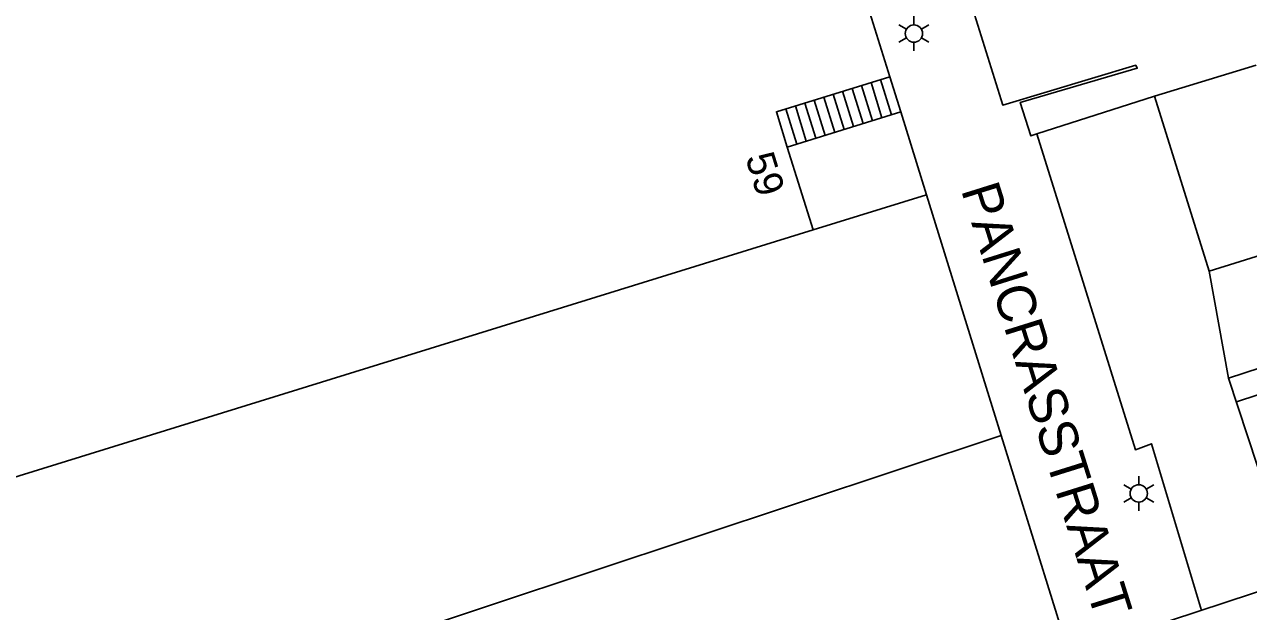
# Model space of a CAD drawing. Extents: x 122462 to 123306, y 485548 to 486417.
# Drawn here: x 122661.2 to 122724.7, y 486167.9 to 486198.4 of the extents above; entities that cross this region are included whole.
import ezdxf

# ---------------------------------------------------------------- set-up
doc = ezdxf.new("R2010")
doc.units = 0
for name, color, linetype in [('B-WE-AL-WERKGRENS-G', 7, 'Continuous'), ('B-WE-IE-MEUBILAIR_WEGMEUBILAIR_VERKEERSBORD-S', 7, 'Continuous'), ('Level 1', 7, 'Continuous'), ('Level 17', 7, 'Continuous'), ('Level 31', 7, 'Continuous'), ('Level 33', 7, 'Continuous'), ('Level 4', 7, 'Continuous'), ('Level 50', 7, 'Continuous'), ('N werkgrens', 7, 'Continuous'), ('N-WE-AL-T25', 7, 'Continuous'), ('N-WE-GR-BOOM_DOORWORTELBARE RUIMTE-G', 7, 'Continuous')]:
    doc.layers.add(name, color=color, linetype=linetype)

msp = doc.modelspace()

# ---------------------------------------------------------------- linework, layer by layer
at = {"layer": 'B-WE-AL-WERKGRENS-G'}
msp.add_lwpolyline([(122857.632, 486078.279), (122830.484, 486160.606), (122900.937, 486183.81), (122887.855, 486222.555), (122665.445, 486149.273), (122678.196, 486110.449), (122807.072, 486152.895), (122835.324, 486068.154)], dxfattribs=at)
at = {"layer": 'Level 1'}
for p, q in [((122702.294, 486207.955), (122706.11, 486195.719)), ((122725.118, 486196.312), (122719.85, 486194.699)), ((122719.85, 486194.699), (122722.685, 486185.626)), ((122700.779, 486192.059), (122702.13, 486187.759)), ((122702.13, 486187.759), (122708.009, 486189.59)), ((122708.009, 486189.59), (122711.887, 486177.083)), ((122722.685, 486185.626), (122727.035, 486186.985)), ((122727.016, 486181.156), (122723.689, 486180.059)), ((122723.689, 486180.059), (122727.121, 486169.595))]:
    msp.add_line(p, q, dxfattribs=at)
for points in [[(122706.11, 486195.719), (122700.214, 486193.893), (122700.779, 486192.059)], [(122711.887, 486177.083), (122715.406, 486165.734)]]:
    msp.add_lwpolyline(points, dxfattribs=at)
at = {"layer": 'Level 17'}
msp.add_line((122719.85, 486194.699), (122713.74, 486192.745), dxfattribs=at)
for points in [[(122713.74, 486192.745), (122713.421, 486192.643), (122712.875, 486194.383), (122718.945, 486196.153), (122718.874, 486196.31), (122711.969, 486194.245), (122710.502, 486198.949), (122710.098, 486200.244), (122712.007, 486200.847), (122712.285, 486199.973)], [(122713.74, 486192.745), (122718.856, 486176.345), (122719.681, 486176.651), (122722.283, 486168)]]:
    msp.add_lwpolyline(points, dxfattribs=at)
at = {"layer": 'Level 31'}
for p, q in [((122706.11, 486195.719), (122706.679, 486193.89)), ((122706.679, 486193.89), (122700.779, 486192.059))]:
    msp.add_line(p, q, dxfattribs=at)
at = {"layer": 'Level 33'}
for p, q in [((122704.146, 486195.112), (122704.714, 486193.281)), ((122704.638, 486195.264), (122705.206, 486193.433)), ((122705.128, 486195.417), (122705.696, 486193.585)), ((122705.62, 486195.569), (122706.188, 486193.738)), ((122702.18, 486194.503), (122702.748, 486192.671)), ((122702.672, 486194.655), (122703.24, 486192.824)), ((122703.163, 486194.807), (122703.731, 486192.976)), ((122703.654, 486194.96), (122704.222, 486193.128)), ((122700.706, 486194.045), (122701.274, 486192.214)), ((122701.198, 486194.198), (122701.766, 486192.367)), ((122701.689, 486194.35), (122702.257, 486192.519))]:
    msp.add_line(p, q, dxfattribs=at)
at = {"layer": 'Level 4'}
msp.add_lwpolyline([(122634.662, 486153.891), (122630.945, 486165.712), (122702.13, 486187.759)], dxfattribs=at)
at = {"layer": 'Level 50'}
for p, q in [((122706.963, 486198.184), (122706.573, 486198.409)), ((122707.353, 486198.409), (122707.353, 486198.859)), ((122708.132, 486198.409), (122707.742, 486198.184)), ((122706.963, 486197.734), (122706.573, 486197.509)), ((122708.132, 486197.509), (122707.742, 486197.734)), ((122707.353, 486197.059), (122707.353, 486197.509)), ((122719.028, 486174.523), (122719.028, 486174.973)), ((122718.638, 486174.298), (122718.248, 486174.523)), ((122719.807, 486174.523), (122719.417, 486174.298)), ((122718.638, 486173.848), (122718.248, 486173.623)), ((122719.028, 486173.173), (122719.028, 486173.623)), ((122719.807, 486173.623), (122719.417, 486173.848))]:
    msp.add_line(p, q, dxfattribs=at)
for centre in [(122707.353, 486197.959), (122719.028, 486174.073)]:
    msp.add_circle(centre, 0.45, dxfattribs=at)
at = {"layer": 'N werkgrens'}
for p, q in [((122706.679, 486193.89), (122708.009, 486189.59)), ((122722.685, 486185.626), (122723.689, 486180.059))]:
    msp.add_line(p, q, dxfattribs=at)
at = {"layer": 'N-WE-AL-T25'}
for p, q in [((122658.143, 486159.234), (122711.887, 486177.083)), ((122711.887, 486177.083), (122711.888, 486177.083))]:
    msp.add_line(p, q, dxfattribs=at)
msp.add_lwpolyline([(122724.096, 486178.827), (122727.42, 486179.922), (122727.016, 486181.156)], dxfattribs=at)

# ---------------------------------------------------------------- texts
at = {"layer": 'B-WE-IE-MEUBILAIR_WEGMEUBILAIR_VERKEERSBORD-S'}
msp.add_text('59', height=1.5, rotation=287.21824, dxfattribs=at).set_placement((122698.594, 486191.52))
at = {"layer": 'N-WE-GR-BOOM_DOORWORTELBARE RUIMTE-G'}
msp.add_text('PANCRASSTRAAT', height=2, rotation=287.40396, dxfattribs=at).set_placement((122709.787, 486189.847))

doc.saveas('drawing.dxf')
